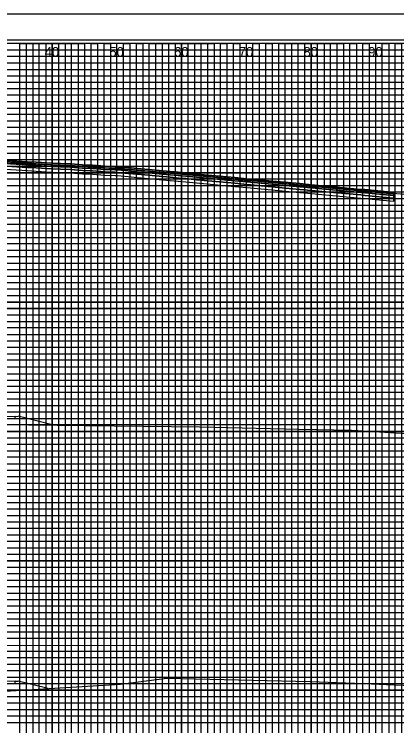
# Model space of a CAD drawing. Extents: x -13 to 760, y -5 to 1491.
# Drawn here: x 194.1 to 253.2, y 1380.5 to 1490.5 of the extents above; entities that cross this region are included whole.
import ezdxf

# ---------------------------------------------------------------- set-up
doc = ezdxf.new("R2010")
doc.units = 0
for name, color, linetype in [('Exist XS Ground Line', 7, 'Continuous'), ('Prop CMT Pvmt Course 1', 7, 'Continuous'), ('Prop CMT Pvmt Course 2', 7, 'Continuous'), ('Prop CMT Pvmt Course 3', 7, 'Continuous'), ('Prop CMT Pvmt Course 4', 7, 'Continuous'), ('Prop Conc 4in Sidewalk', 7, 'Continuous'), ('Prop XS Finish Grade', 7, 'Continuous'), ('Prop XS Offset Labels', 7, 'Continuous'), ('Scratch_Level_6', 7, 'Continuous'), ('Scratch_Level_9', 7, 'Continuous'), ('Sheet Cross Section CELL', 7, 'Continuous'), ('Sheet Cross Section Grid Major CELL', 7, 'Continuous'), ('Sheet Cross Section Grid Middle CELL', 7, 'Continuous'), ('Sheet Cross Section Grid Minor 1 CELL', 7, 'Continuous'), ('Sheet Cross Section Grid Minor 2 CELL', 7, 'Continuous'), ('Sheet Cutting Line CELL', 7, 'Continuous'), ('Sheet DOT Grid CELL', 7, 'Continuous'), ('Sheet Plot Border Inside CELL', 7, 'Continuous'), ('Sheet Plot Border Outside CELL', 7, 'Continuous')]:
    doc.layers.add(name, color=color, linetype=linetype)

msp = doc.modelspace()

# ---------------------------------------------------------------- linework, layer by layer
at = {"layer": 'Exist XS Ground Line'}
for points in [[(190.15, 1467.62), (197.72, 1467.36), (203.9, 1467.01), (208.74, 1466.71), (211.93, 1466.54), (214.93, 1466.3), (217.84, 1466.04), (241.92, 1463.83), (247.29, 1463.35), (259.82, 1462.2)], [(190.15, 1467.62), (197.72, 1467.36), (203.9, 1467.01), (208.74, 1466.71), (211.93, 1466.54), (214.93, 1466.3), (217.84, 1466.04), (241.92, 1463.83), (247.29, 1463.35), (259.82, 1462.2)], [(191.92, 1427.11), (222.75, 1426.71), (238.13, 1426.36), (246.25, 1426.22), (247.25, 1426.19), (261.5, 1425.29)], [(191.92, 1427.11), (222.75, 1426.71), (238.13, 1426.36), (246.25, 1426.22), (247.25, 1426.19), (261.5, 1425.29)], [(192.7, 1385.88), (210.57, 1386.95), (217.7, 1387.86), (239.86, 1387.36), (248.13, 1387.06), (252.84, 1386.84), (289.8, 1385.46)], [(192.7, 1385.88), (210.57, 1386.95), (217.7, 1387.86), (239.86, 1387.36), (248.13, 1387.06), (252.84, 1386.84), (289.8, 1385.46)]]:
    msp.add_lwpolyline(points, dxfattribs=at)
at = {"layer": 'Prop CMT Pvmt Course 1'}
msp.add_lwpolyline([(184.75, 1468.18), (196.18, 1467.47), (197.51, 1467.4), (199.91, 1467.25), (201.27, 1467.18), (202.81, 1467.12), (204.66, 1466.97), (206.21, 1466.92), (208.14, 1466.77), (209.72, 1466.73), (210.06, 1466.7), (210.63, 1466.65), (211.73, 1466.55), (213.14, 1466.42), (213.73, 1466.37), (218.2, 1465.95), (220.06, 1465.78), (220.63, 1465.72), (222.31, 1465.57), (228.23, 1465.01), (230.06, 1464.84), (230.64, 1464.79), (232.28, 1464.64), (238.27, 1464.08), (240.06, 1463.91), (240.65, 1463.86), (241.65, 1463.76), (247.69, 1463.2), (248.29, 1463.15), (252.79, 1462.73), (252.79, 1462.98), (248.29, 1463.4), (247.69, 1463.45), (241.65, 1464.01), (240.65, 1464.11), (240.06, 1464.16), (238.27, 1464.33), (232.28, 1464.89), (230.64, 1465.04), (230.06, 1465.09), (228.23, 1465.26), (222.31, 1465.82), (220.63, 1465.97), (220.06, 1466.03), (218.2, 1466.2), (213.73, 1466.62), (213.14, 1466.67), (211.73, 1466.8), (210.63, 1466.9), (210.06, 1466.95), (209.72, 1466.98), (208.14, 1467.02), (206.21, 1467.17), (204.66, 1467.22), (202.81, 1467.37), (201.27, 1467.43), (199.91, 1467.5), (197.51, 1467.65), (196.18, 1467.72), (184.75, 1468.43)], dxfattribs=at)
at = {"layer": 'Prop CMT Pvmt Course 2'}
msp.add_lwpolyline([(184.75, 1467.93), (196.18, 1467.22), (197.51, 1467.15), (199.91, 1467), (201.27, 1466.93), (202.81, 1466.87), (204.66, 1466.72), (206.21, 1466.67), (208.14, 1466.52), (209.72, 1466.48), (210.06, 1466.45), (210.63, 1466.4), (211.73, 1466.3), (213.14, 1466.17), (213.73, 1466.12), (218.2, 1465.7), (220.06, 1465.53), (220.63, 1465.47), (222.31, 1465.32), (228.23, 1464.76), (230.06, 1464.59), (230.64, 1464.54), (232.28, 1464.39), (238.27, 1463.83), (240.06, 1463.66), (240.65, 1463.61), (241.65, 1463.51), (247.69, 1462.95), (248.29, 1462.9), (252.79, 1462.48), (252.79, 1462.73), (248.29, 1463.15), (247.69, 1463.2), (241.65, 1463.76), (240.65, 1463.86), (240.06, 1463.91), (238.27, 1464.08), (232.28, 1464.64), (230.64, 1464.79), (230.06, 1464.84), (228.23, 1465.01), (222.31, 1465.57), (220.63, 1465.72), (220.06, 1465.78), (218.2, 1465.95), (213.73, 1466.37), (213.14, 1466.42), (211.73, 1466.55), (210.63, 1466.65), (210.06, 1466.7), (209.72, 1466.73), (208.14, 1466.77), (206.21, 1466.92), (204.66, 1466.97), (202.81, 1467.12), (201.27, 1467.18), (199.91, 1467.25), (197.51, 1467.4), (196.18, 1467.47), (184.75, 1468.18)], dxfattribs=at)
at = {"layer": 'Prop CMT Pvmt Course 3'}
msp.add_lwpolyline([(184.75, 1467.55), (196.18, 1466.85), (197.51, 1466.77), (199.91, 1466.62), (201.27, 1466.56), (202.81, 1466.5), (204.66, 1466.35), (206.21, 1466.3), (208.14, 1466.14), (209.72, 1466.1), (210.06, 1466.07), (210.63, 1466.02), (211.73, 1465.92), (213.14, 1465.8), (213.73, 1465.74), (218.2, 1465.32), (220.06, 1465.15), (220.63, 1465.1), (222.31, 1464.94), (228.23, 1464.39), (230.06, 1464.22), (230.64, 1464.17), (232.28, 1464.01), (238.27, 1463.45), (240.06, 1463.29), (240.65, 1463.23), (241.65, 1463.14), (247.69, 1462.58), (248.29, 1462.52), (252.79, 1462.1), (252.79, 1462.48), (248.29, 1462.9), (247.69, 1462.95), (241.65, 1463.51), (240.65, 1463.61), (240.06, 1463.66), (238.27, 1463.83), (232.28, 1464.39), (230.64, 1464.54), (230.06, 1464.59), (228.23, 1464.76), (222.31, 1465.32), (220.63, 1465.47), (220.06, 1465.53), (218.2, 1465.7), (213.73, 1466.12), (213.14, 1466.17), (211.73, 1466.3), (210.63, 1466.4), (210.06, 1466.45), (209.72, 1466.48), (208.14, 1466.52), (206.21, 1466.67), (204.66, 1466.72), (202.81, 1466.87), (201.27, 1466.93), (199.91, 1467), (197.51, 1467.15), (196.18, 1467.22), (184.75, 1467.93)], dxfattribs=at)
at = {"layer": 'Prop CMT Pvmt Course 4'}
msp.add_lwpolyline([(184.75, 1467.05), (196.18, 1466.35), (197.51, 1466.27), (199.91, 1466.12), (201.27, 1466.06), (202.81, 1466), (204.66, 1465.85), (206.21, 1465.8), (208.14, 1465.64), (209.72, 1465.6), (210.06, 1465.57), (210.63, 1465.52), (211.73, 1465.42), (213.14, 1465.3), (213.73, 1465.24), (218.2, 1464.82), (220.06, 1464.65), (220.63, 1464.6), (222.31, 1464.44), (228.23, 1463.89), (230.06, 1463.72), (230.64, 1463.67), (232.28, 1463.51), (238.27, 1462.95), (240.06, 1462.79), (240.65, 1462.73), (241.65, 1462.64), (247.69, 1462.08), (248.29, 1462.02), (252.79, 1461.6), (252.79, 1462.1), (248.29, 1462.52), (247.69, 1462.58), (241.65, 1463.14), (240.65, 1463.23), (240.06, 1463.29), (238.27, 1463.45), (232.28, 1464.01), (230.64, 1464.17), (230.06, 1464.22), (228.23, 1464.39), (222.31, 1464.94), (220.63, 1465.1), (220.06, 1465.15), (218.2, 1465.32), (213.73, 1465.74), (213.14, 1465.8), (211.73, 1465.92), (210.63, 1466.02), (210.06, 1466.07), (209.72, 1466.1), (208.14, 1466.14), (206.21, 1466.3), (204.66, 1466.35), (202.81, 1466.5), (201.27, 1466.56), (199.91, 1466.62), (197.51, 1466.77), (196.18, 1466.85), (184.75, 1467.55)], dxfattribs=at)
at = {"layer": 'Prop Conc 4in Sidewalk'}
for points in [[(189.25, 1428.25), (189.24, 1427.92), (194.26, 1428.02), (194.25, 1428.35), (189.25, 1428.25)], [(189.25, 1387.33), (189.24, 1387), (194.26, 1387.1), (194.25, 1387.43), (189.25, 1387.33)]]:
    msp.add_lwpolyline(points, dxfattribs=at)
at = {"layer": 'Prop XS Finish Grade'}
for points in [[(194.25, 1428.35), (194.75, 1428.36)], [(200.18, 1427), (200.18, 1427), (194.75, 1428.36)], [(194.25, 1387.43), (194.75, 1387.44)], [(199.38, 1386.28), (194.75, 1387.44), (194.75, 1387.44)]]:
    msp.add_lwpolyline(points, dxfattribs=at)
at = {"layer": 'Scratch_Level_6'}
msp.add_lwpolyline([(184.75, 1468.43), (196.18, 1467.72), (197.51, 1467.65), (199.91, 1467.5), (201.27, 1467.43), (202.81, 1467.37), (204.66, 1467.22), (206.21, 1467.17), (208.14, 1467.02), (209.72, 1466.98), (210.06, 1466.95), (210.63, 1466.9), (211.73, 1466.8), (213.14, 1466.67), (213.73, 1466.62), (218.2, 1466.2), (220.06, 1466.03), (220.63, 1465.97), (222.31, 1465.82), (228.23, 1465.26), (230.06, 1465.09), (230.64, 1465.04), (232.28, 1464.89), (238.27, 1464.33), (240.06, 1464.16), (240.65, 1464.11), (241.65, 1464.01), (247.69, 1463.45), (248.29, 1463.4), (252.79, 1462.98)], dxfattribs=at)
at = {"layer": 'Sheet Cross Section CELL'}
msp.add_lwpolyline([(320, 1486.02), (0, 1486.02), (0, 1276.02), (320, 1276.02)], close=True, dxfattribs=at)
at = {"layer": 'Sheet Cross Section Grid Major CELL'}
for p, q in [((210, 1486.02), (200, 1486.02)), ((200, 1486.02), (200, 1276.02)), ((210, 1276.02), (210, 1486.02)), ((230, 1486.02), (220, 1486.02)), ((220, 1486.02), (220, 1276.02)), ((230, 1276.02), (230, 1486.02)), ((250, 1486.02), (240, 1486.02)), ((240, 1486.02), (240, 1276.02)), ((250, 1276.02), (250, 1486.02))]:
    msp.add_line(p, q, dxfattribs=at)
for points in [[(0, 1476.02), (320, 1476.02), (320, 1466.02), (0, 1466.02)], [(0, 1456.02), (320, 1456.02), (320, 1446.02), (0, 1446.02)], [(0, 1436.02), (320, 1436.02), (320, 1426.02), (0, 1426.02)], [(0, 1416.02), (320, 1416.02), (320, 1406.02), (0, 1406.02)], [(0, 1396.02), (320, 1396.02), (320, 1386.02), (0, 1386.02)]]:
    msp.add_lwpolyline(points, dxfattribs=at)
at = {"layer": 'Sheet Cross Section Grid Middle CELL'}
for points in [[(195, 1276.02), (195, 1486.02), (205, 1486.02), (205, 1276.02)], [(215, 1276.02), (215, 1486.02), (225, 1486.02), (225, 1276.02)], [(235, 1276.02), (235, 1486.02), (245, 1486.02), (245, 1276.02)], [(0, 1481.02), (275, 1481.02)], [(0, 1461.02), (320, 1461.02), (320, 1471.02), (0, 1471.02)], [(0, 1441.02), (320, 1441.02), (320, 1451.02), (0, 1451.02)], [(0, 1421.02), (320, 1421.02), (320, 1431.02), (0, 1431.02)], [(0, 1401.02), (320, 1401.02), (320, 1411.02), (0, 1411.02)], [(0, 1381.02), (320, 1381.02), (320, 1391.02), (0, 1391.02)]]:
    msp.add_lwpolyline(points, dxfattribs=at)
at = {"layer": 'Sheet Cross Section Grid Minor 1 CELL'}
for p, q in [((0, 1485.02), (260, 1485.02)), ((260, 1484), (0, 1484)), ((0, 1483.02), (260, 1483.02)), ((260, 1481.91), (0, 1481.91)), ((0, 1480.02), (320, 1480.02))]:
    msp.add_line(p, q, dxfattribs=at)
for points in [[(0, 1479.02), (270, 1479.02), (320, 1479.02), (320, 1478.02), (0, 1478.02)], [(0, 1477.02), (320, 1477.02), (320, 1475.02), (0, 1475.02)], [(0, 1474.02), (320, 1474.02), (320, 1473.02), (0, 1473)], [(0, 1472.02), (320, 1472.02), (320, 1470.02), (0, 1470.02)], [(0, 1469.02), (320, 1469.02), (320, 1468.02), (0, 1468.02)], [(0, 1467.02), (320, 1467.02), (320, 1465.02), (0, 1465.02)], [(0, 1464.02), (320, 1464.02), (320, 1463.02), (0, 1463.02)], [(0, 1462.02), (320, 1462.02), (320, 1460.02), (0, 1460.02)], [(0, 1459.02), (320, 1459.02), (320, 1458.02), (0, 1458.02)], [(0, 1457.02), (320, 1457.02), (320, 1455.02), (0, 1455.02)], [(0, 1454.02), (320, 1454.02), (320, 1453.02), (0, 1453.02)], [(0, 1452.02), (320, 1452.02), (320, 1449.97), (320, 1449.02), (320, 1448.02), (0, 1448.02)], [(0, 1450.02), (320, 1450.02), (320, 1449.02), (0, 1449.02)], [(0, 1447.02), (320, 1447.02), (320, 1445.02), (0, 1445.05)], [(0, 1445.05), (320, 1445.02), (320, 1444.02), (0, 1444.02)], [(0, 1443.02), (320, 1443.02), (320, 1442.02), (0, 1442.02)], [(0, 1440.02), (320, 1440.02), (320, 1439.02), (0, 1439.02)], [(0, 1438.02), (320, 1438.02), (320, 1437.02), (0, 1437.02)], [(-0.07, 1434.91), (320, 1434.91), (320, 1433.9), (-0.07, 1433.9)], [(0, 1433.02), (320, 1433.02), (320, 1432.02), (0, 1432.02)], [(0, 1430.02), (320, 1430.02), (320, 1429.02), (0, 1429.02)], [(0, 1428.02), (320, 1428.02), (320, 1427.02), (0, 1427.02)], [(0, 1425.02), (320, 1425.02), (320, 1424.02), (0, 1424.02)], [(0, 1423.02), (320, 1423.02), (320, 1422.02), (0, 1422.02)], [(0, 1420.02), (320, 1420.02), (320, 1419.02), (0, 1419.02)], [(0, 1418.02), (320, 1418.02), (320, 1417.02), (0, 1417.02)], [(0, 1415.02), (320, 1415.02), (319.99, 1414), (0, 1414.02)], [(0, 1413.02), (320, 1413.02), (320, 1412.02), (0, 1412.02)], [(0, 1410.02), (320, 1410.02), (320, 1409.02), (0, 1409.02)], [(0, 1408.02), (320, 1408.02), (320, 1407.02), (0, 1407.02)], [(0, 1405.02), (320, 1405.02), (320, 1404.02), (0, 1404.02)], [(0, 1403.02), (320, 1403.02), (320, 1402.02), (0, 1402.02)], [(0, 1400.02), (320, 1400.02), (320, 1399.02), (0, 1399.02)], [(0, 1398.02), (320, 1398.02), (320, 1397.02), (0, 1397.02)], [(0, 1395.02), (320, 1395.02), (320, 1394.02), (0, 1394.02)], [(0, 1393.01), (320.07, 1392.93), (320, 1392.02), (0, 1392.02)], [(0, 1390.02), (320, 1390.02), (320, 1389.02), (0, 1389.02)], [(0, 1388.02), (320, 1388.02), (320, 1387.02), (0, 1387.02)], [(0, 1385.02), (320, 1385.02), (320, 1384.02), (0, 1384.02)], [(0, 1383.02), (320, 1383.02), (320, 1382.02), (0, 1382.02)]]:
    msp.add_lwpolyline(points, dxfattribs=at)
at = {"layer": 'Sheet Cross Section Grid Minor 2 CELL'}
for points in [[(195, 1276.02), (196, 1276.02), (196, 1486.02), (197, 1486.02), (197, 1276.02)], [(197, 1276.02), (198, 1276.02), (198, 1486.02), (199, 1486.02), (199, 1276.02)], [(200, 1276.02), (201, 1276.02), (201, 1486.02), (202, 1486.02), (202, 1276.02)], [(202, 1276.02), (203, 1276.02), (203, 1486.02), (204, 1486.02), (204, 1276.02)], [(205, 1276.02), (206, 1276.02), (206, 1486.02), (207, 1486.02), (207, 1276.02)], [(207, 1276.02), (208, 1276.02), (208, 1486.02), (209, 1486.02), (209, 1276.02)], [(210, 1276.02), (211, 1276.02), (211, 1486.02), (212, 1486.02), (212, 1276.02)], [(212, 1276.02), (213, 1276.02), (213, 1486.02), (214, 1486.02), (214, 1276.02)], [(215, 1276.02), (216, 1276.02), (216, 1486.02), (217, 1486.02), (217, 1276.02)], [(217, 1276.02), (218, 1276.02), (218, 1486.02), (219, 1486.02), (219, 1276.02)], [(220, 1276.02), (221, 1276.02), (221, 1486.02), (222, 1486.02), (222, 1276.02)], [(222, 1276.02), (223, 1276.02), (223, 1486.02), (224, 1486.02), (224, 1276.02)], [(225, 1276.02), (226, 1276.02), (226, 1486.02), (227, 1486.02), (227, 1276.02)], [(227, 1276.02), (228, 1276.02), (228, 1486.02), (229, 1486.02), (229, 1276.02)], [(230, 1276.02), (231, 1276.02), (231, 1486.02), (232, 1486.02), (232, 1276.02)], [(232, 1276.02), (233, 1276.02), (233, 1486.02), (234, 1486.02), (234, 1276.02)], [(235, 1276.02), (236, 1276.02), (236, 1486.02), (237, 1486.02), (237, 1276.02)], [(237, 1276.02), (238, 1276.02), (238, 1486.02), (239, 1486.02), (239, 1276.02)], [(240, 1276.02), (241, 1276.02), (241, 1486.02), (242, 1486.02), (242, 1276.02)], [(242, 1276.02), (243, 1276.02), (243, 1486.02), (244, 1486.02), (244, 1276.02)], [(245, 1276.02), (246, 1276.02), (246, 1486.02), (247, 1486.02), (247, 1276.02)], [(247, 1276.02), (248, 1276.02), (248, 1486.02), (249, 1486.02), (249, 1276.02)], [(250, 1276.02), (251, 1276.02), (251, 1486.02), (252, 1486.02), (252, 1276.02)], [(252, 1276.02), (253, 1276.02), (253, 1486.02), (254, 1486.02), (254, 1276.02)]]:
    msp.add_lwpolyline(points, dxfattribs=at)
at = {"layer": 'Sheet Cutting Line CELL'}
msp.add_line((323.3, 1490.52), (-13.4, 1490.52), dxfattribs=at)
at = {"layer": 'Sheet DOT Grid CELL'}
for p, q in [((200, 1276.02), (200, 1486.02)), ((210, 1276.02), (210, 1486.02)), ((220, 1276.02), (220, 1486.02)), ((230, 1276.02), (230, 1486.02)), ((240, 1276.02), (240, 1486.02)), ((250, 1276.02), (250, 1486.02)), ((0, 1476.02), (320, 1476.02)), ((0, 1466.02), (320, 1466.02)), ((0, 1456.02), (320, 1456.02)), ((0, 1446.02), (320, 1446.02)), ((0, 1436.02), (320, 1436.02)), ((0, 1426.02), (320, 1426.02)), ((0, 1416.02), (320, 1416.02)), ((0, 1406.02), (320, 1406.02)), ((0, 1396.02), (320, 1396.02)), ((0, 1386.02), (320, 1386.02))]:
    msp.add_line(p, q, dxfattribs=at)
at = {"layer": 'Sheet Plot Border Inside CELL'}
msp.add_lwpolyline([(-10.8, 1275.52), (322.4, 1275.52), (322.4, 1486.52), (-10.8, 1486.52)], close=True, dxfattribs=at)
at = {"layer": 'Sheet Plot Border Outside CELL'}
msp.add_lwpolyline([(-13.4, 1271.52), (323.3, 1271.52), (323.3, 1490.52), (-13.4, 1490.52)], close=True, dxfattribs=at)

# ---------------------------------------------------------------- texts
at = {"layer": 'Prop XS Offset Labels'}
for s, p in [('40', (198.83, 1483.95)), ('50', (208.83, 1483.95)), ('60', (218.83, 1483.95)), ('70', (228.83, 1483.95)), ('80', (238.83, 1483.95)), ('90', (248.83, 1483.95))]:
    msp.add_text(s, height=1.5, dxfattribs=at).set_placement(p)
at = {"layer": 'Scratch_Level_9'}
for p in [(194.25, 1428.35), (200.18, 1427), (194.25, 1387.43), (199.38, 1386.28)]:
    msp.add_text('X', height=0.0025, dxfattribs=at).set_placement(p)

doc.saveas('drawing.dxf')
